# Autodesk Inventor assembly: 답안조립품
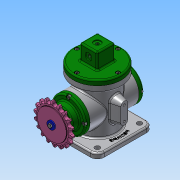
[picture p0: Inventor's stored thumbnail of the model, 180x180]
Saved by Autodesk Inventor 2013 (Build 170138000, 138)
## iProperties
Created: 2021-03
Part Number: 답안조립품
Document SubType Name: Assembly
Designer: Administrator
Author: Administrator
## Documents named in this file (19)
- C:\Users\Administrator\Desktop\710306V1005\답안조립품.iam
- C:\Users\Administrator\Desktop\710306V1005\본체.ipt
- C:\Users\Administrator\Desktop\710306V1005\베어링 17 x 40 x 12.ipt
- C:\Users\Administrator\Desktop\710306V1005\볼트 M4 x 10.ipt
- C:\Users\Administrator\Desktop\710306V1005\앞커버.ipt
- C:\Users\Administrator\Desktop\710306V1005\오일 실 17 30 8.ipt
- C:\Users\Administrator\Desktop\710306V1005\뒤커버.ipt
- C:\Users\Administrator\Desktop\710306V1005\덮개.ipt
- C:\Users\Administrator\Desktop\710306V1005\링크.ipt
- C:\Users\Administrator\Desktop\710306V1005\슬라이더.ipt
- C:\Users\Administrator\Desktop\710306V1005\클레비스 핀 6 x 22.ipt
- 클레비스 핀 6 x 22.ipt
- C:\Users\Administrator\Desktop\710306V1005\키 4 x 4 x 12.ipt
- C:\Users\Administrator\Desktop\710306V1005\편심축.ipt
- C:\Users\Administrator\Desktop\710306V1005\E-링.ipt
- C:\Users\Administrator\Desktop\710306V1005\멈춤나사 M3.ipt
- C:\Users\Administrator\Desktop\710306V1005\볼트 M4 x 8.ipt
- C:\Users\Administrator\Desktop\710306V1005\스프로킷.ipt
- C:\Users\Administrator\Desktop\710306V1005\와셔 4x16.ipt
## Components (1 placed, 1 different names)
1. E-링:1
